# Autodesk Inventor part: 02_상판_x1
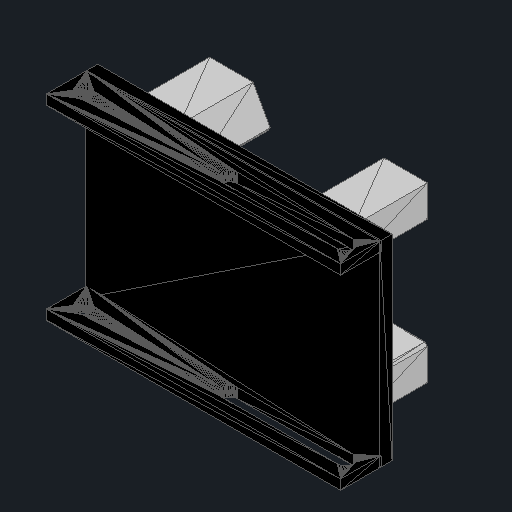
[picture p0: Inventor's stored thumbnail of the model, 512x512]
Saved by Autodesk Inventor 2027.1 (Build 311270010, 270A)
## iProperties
Created: 2026-11
Part Number: 02_상판_x1
Material: 일반
Document SubType Name: Modeling
Designer: djshs
Density: 1 g/cm^3
Appearance: 기본값
Author: djshs
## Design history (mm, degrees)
node "02_상판_x1"
  node "MeshFeature1"
